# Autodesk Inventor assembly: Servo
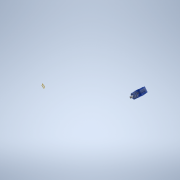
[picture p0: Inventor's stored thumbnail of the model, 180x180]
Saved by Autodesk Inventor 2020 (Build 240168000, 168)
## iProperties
Created: 2002-01
Part Number: Servo
Document SubType Name: Assemblage
Designer: Philippe
Shininess: 41.0
Angle Display Precision: 2
Document Length Units: 11269
Document Angle Units: 11279
Document Time Units: 11290
Document Mass Units: 11283
Document Length Units Precision: 3
Document Angle Units Precision: 2
Density: 0.0
Volumn: 0.0
Area: 0.0
PropertySet Name: Model Information
Control State: 0
Master: False
Checked Out: False
Author: Philippe
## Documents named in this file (13)
- C:\Users\bruno\OneDrive\Bureau\Robot-Inventor\Robot-equillibrage\Servo\Servo.iam
- C:\Users\bruno\OneDrive\Bureau\Robot-Inventor\Robot-equillibrage\Servo\Couvercle inférieur.ipt
- C:\Users\bruno\OneDrive\Bureau\Robot-Inventor\Robot-equillibrage\Servo\Boitier.ipt
- C:\Users\bruno\OneDrive\Bureau\Robot-Inventor\Robot-equillibrage\Servo\Couvercle supérieur.ipt
- C:\Users\bruno\OneDrive\Bureau\Robot-Inventor\Robot-equillibrage\Servo\Moteur.ipt
- C:\Users\bruno\OneDrive\Bureau\Robot-Inventor\Robot-equillibrage\Servo\Pignon moteur.ipt
- C:\Users\bruno\OneDrive\Bureau\Robot-Inventor\Robot-equillibrage\Servo\Axe central.ipt
- C:\Users\bruno\OneDrive\Bureau\Robot-Inventor\Robot-equillibrage\Servo\Mobile 2-3.ipt
- C:\Users\bruno\OneDrive\Bureau\Robot-Inventor\Robot-equillibrage\Servo\Mobile 4-5.ipt
- C:\Users\bruno\OneDrive\Bureau\Robot-Inventor\Robot-equillibrage\Servo\Potentiomètre.ipt
- C:\Users\bruno\OneDrive\Bureau\Robot-Inventor\Robot-equillibrage\Servo\Mobile 6-7.ipt
- C:\Users\bruno\OneDrive\Bureau\Robot-Inventor\Robot-equillibrage\Servo\Roue 8.ipt
- C:\Users\bruno\OneDrive\Bureau\Robot-Inventor\Robot-equillibrage\Servo\ISO 7049 - ST 2.2 x 4.5 - F - H.ipt
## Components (12 placed, 12 different names)
1. Boitier:1 — Plaquage1, Plaquage2, Placage:1, Placage:2, Logement:1, Angle:1, Placage:3, Placage:4, Placage:6, Orientation, Placage:7, Logement:3, Logement:4
2. Couvercle inférieur:1 — Plaquage1, Placage:3, Placage:4
3. Couvercle supérieur:1 — Plaquage2, Placage:1, Placage:2, Angle:5
4. Moteur:1 — Logement:1, Angle:1, Logement:2
5. Pignon moteur:1 — Logement:2, Rotation:1
6. Axe central:1 — Angle:2, Placage:5, Logement:3, Angle:3, Placage:9
7. Mobile 2-3:1 — Angle:2, Placage:5, Placage:6, Rotation:1, Placage:8, Rotation:2, Placage:10
8. Mobile 4-5:1 — Orientation, Placage:7, Placage:8, Rotation:2, Rotation:3, Placage:11
9. Potentiomètre:1 — Logement:4, Placage:12
10. Mobile 6-7:1 — Angle:3, Placage:9, Placage:10, Rotation:3, Rotation:4
11. Roue 8:1 — Placage:11, Placage:12, Rotation:4, Angle:5
12. ISO 7049 - ST 2.2 x 4.5 - F - H:1
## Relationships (27: Mate 14, Angle 5, Insert 4, RelateRotation 4)
- Plaquage1 [Mate]: Boitier:1 ↔ Couvercle inférieur:1
- Plaquage2 [Mate]: Boitier:1 ↔ Couvercle supérieur:1
- Placage:1 [Mate]: Boitier:1 ↔ Couvercle supérieur:1
- Placage:2 [Mate]: Boitier:1 ↔ Couvercle supérieur:1
- Logement:1 [Insert]: Boitier:1 ↔ Moteur:1
- Angle:1: Boitier:1 ↔ Moteur:1
- Placage:3 [Mate]: Boitier:1 ↔ Couvercle inférieur:1
- Placage:4 [Mate]: Boitier:1 ↔ Couvercle inférieur:1
- Logement:2 [Insert]: Moteur:1 ↔ Pignon moteur:1
- Angle:2: Axe central:1 ↔ Mobile 2-3:1
- Placage:5 [Mate]: Axe central:1 ↔ Mobile 2-3:1
- Placage:6 [Mate]: Boitier:1 ↔ Mobile 2-3:1
- Rotation:1 [RelateRotation]: Pignon moteur:1 ↔ Mobile 2-3:1
- Orientation [Angle]: Boitier:1 ↔ Mobile 4-5:1
- Placage:7 [Mate]: Boitier:1 ↔ Mobile 4-5:1
- Placage:8 [Mate]: Mobile 2-3:1 ↔ Mobile 4-5:1
- Logement:3 [Insert]: Boitier:1 ↔ Axe central:1
- Rotation:2 [RelateRotation]: Mobile 2-3:1 ↔ Mobile 4-5:1
- Logement:4 [Insert]: Boitier:1 ↔ Potentiomètre:1
- Angle:3: Axe central:1 ↔ Mobile 6-7:1
- Placage:9 [Mate]: Axe central:1 ↔ Mobile 6-7:1
- Placage:10 [Mate]: Mobile 2-3:1 ↔ Mobile 6-7:1
- Rotation:3 [RelateRotation]: Mobile 4-5:1 ↔ Mobile 6-7:1
- Placage:11 [Mate]: Mobile 4-5:1 ↔ Roue 8:1
- Placage:12 [Mate]: Potentiomètre:1 ↔ Roue 8:1
- Rotation:4 [RelateRotation]: Mobile 6-7:1 ↔ Roue 8:1
- Angle:5: Couvercle supérieur:1 ↔ Roue 8:1
